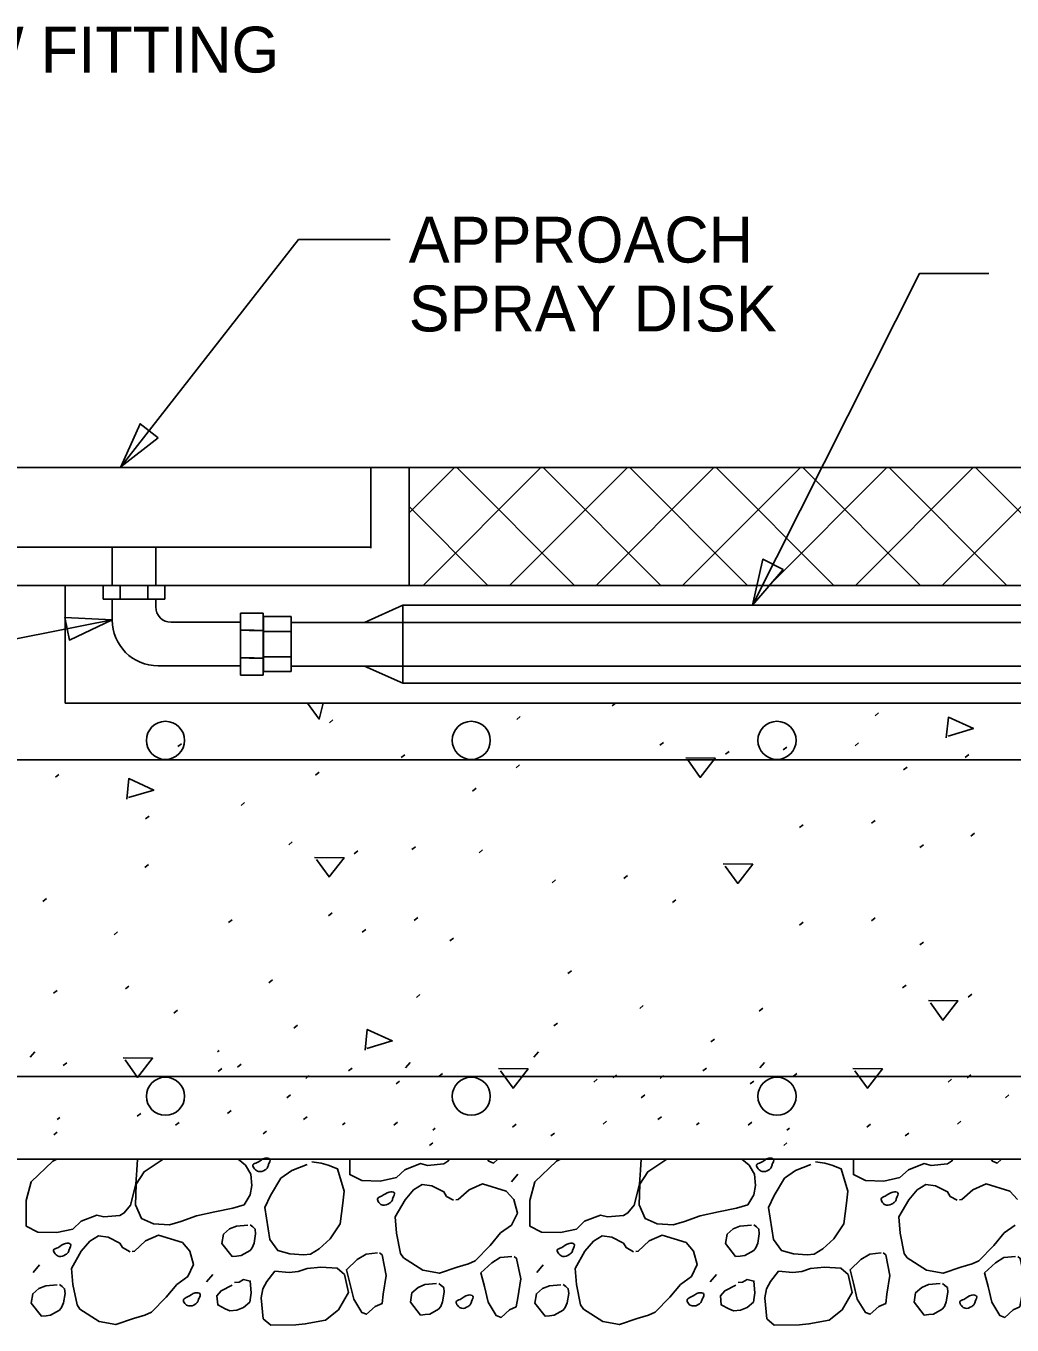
# Model space of a CAD drawing. Extents: x 3239 to 4230, y -4276 to -2494.
# Drawn here: x 3348.5 to 3413, y -4182.4 to -4097.4 of the extents above; entities that cross this region are included whole.
import ezdxf

# ---------------------------------------------------------------- set-up
doc = ezdxf.new("R2010")
doc.units = 0
doc.layers.add('2', color=7, linetype='Continuous')

msp = doc.modelspace()

# ---------------------------------------------------------------- linework, layer by layer
at = {"layer": '2'}
for p, q in [((3367.086, -4126.29), (3310.367, -4126.29)), ((3367.086, -4126.29), (3545.886, -4126.29)), ((3371.086, -4126.29), (3371.086, -4131.565)), ((3373.586, -4126.29), (3373.586, -4133.99)), ((3373.586, -4129.25), (3376.546, -4126.29)), ((3374.502, -4133.99), (3382.202, -4126.29)), ((3376.699, -4126.29), (3384.399, -4133.99)), ((3380.159, -4133.99), (3387.859, -4126.29)), ((3382.355, -4126.29), (3390.055, -4133.99)), ((3385.816, -4133.99), (3393.516, -4126.29)), ((3388.012, -4126.29), (3395.712, -4133.99)), ((3391.473, -4133.99), (3399.173, -4126.29)), ((3393.669, -4126.29), (3401.369, -4133.99)), ((3397.13, -4133.99), (3404.83, -4126.29)), ((3399.326, -4126.29), (3407.026, -4133.99)), ((3402.787, -4133.99), (3410.487, -4126.29)), ((3404.983, -4126.29), (3412.683, -4133.99)), ((3408.444, -4133.99), (3416.144, -4126.29)), ((3410.64, -4126.29), (3418.34, -4133.99)), ((3373.586, -4128.834), (3378.742, -4133.99)), ((3340.086, -4131.49), (3371.086, -4131.49)), ((3354.161, -4131.49), (3354.161, -4133.99)), ((3357.011, -4131.49), (3354.161, -4131.49)), ((3357.011, -4131.49), (3357.011, -4133.99)), ((3314.367, -4133.99), (3373.472, -4133.99)), ((3351.09, -4133.99), (3351.09, -4141.69)), ((3353.561, -4133.99), (3353.561, -4134.89)), ((3357.611, -4133.99), (3353.561, -4133.99)), ((3354.686, -4133.99), (3354.686, -4134.89)), ((3356.486, -4133.99), (3356.486, -4134.89)), ((3357.611, -4133.99), (3357.611, -4134.89)), ((3363.086, -4133.99), (3601.998, -4133.99)), ((3357.611, -4134.89), (3353.561, -4134.89)), ((3354.161, -4134.89), (3354.161, -4136.254)), ((3357.011, -4134.89), (3357.011, -4135.404)), ((3362.557, -4135.804), (3363.457, -4135.804)), ((3362.557, -4135.804), (3362.557, -4139.854)), ((3363.127, -4135.815), (3364.027, -4135.815)), ((3364.027, -4135.815), (3364.027, -4139.865)), ((3373.167, -4136.497), (3373.163, -4135.284)), ((3373.167, -4135.293), (3504.55, -4135.293)), ((3373.167, -4135.293), (3373.167, -4140.387)), ((3358.011, -4136.404), (3362.557, -4136.404)), ((3364.057, -4136.029), (3364.057, -4139.629)), ((3364.057, -4136.029), (3365.857, -4136.029)), ((3365.857, -4136.029), (3365.857, -4139.629)), ((3365.857, -4136.415), (3504.55, -4136.415)), ((3362.557, -4136.929), (3363.457, -4136.929)), ((3363.127, -4136.94), (3364.027, -4136.94)), ((3364.057, -4137.004), (3365.857, -4137.004)), ((3357.161, -4139.254), (3362.557, -4139.254)), ((3362.557, -4138.729), (3363.457, -4138.729)), ((3363.127, -4138.74), (3364.027, -4138.74)), ((3364.057, -4138.654), (3365.857, -4138.654)), ((3365.857, -4139.265), (3504.55, -4139.265)), ((3365.857, -4139.265), (3504.55, -4139.265)), ((3362.557, -4139.854), (3363.457, -4139.854)), ((3363.127, -4139.865), (3364.027, -4139.865)), ((3364.057, -4139.629), (3365.857, -4139.629)), ((3373.167, -4140.387), (3504.55, -4140.387)), ((3351.09, -4141.69), (3512.455, -4141.69)), ((3386.867, -4141.869), (3387.09, -4141.69)), ((3380.623, -4142.754), (3380.856, -4142.567)), ((3404.059, -4142.518), (3404.292, -4142.332)), ((3368.365, -4142.973), (3368.598, -4142.787)), ((3358.463, -4144.534), (3358.696, -4144.348)), ((3389.988, -4144.446), (3390.221, -4144.26)), ((3402.754, -4144.475), (3402.987, -4144.289)), ((3373.071, -4145.256), (3373.304, -4145.07)), ((3394.276, -4145.037), (3394.509, -4144.851)), ((3398.05, -4144.757), (3398.283, -4144.571)), ((3409.953, -4145.244), (3410.186, -4145.058)), ((3311.806, -4145.411), (3542.451, -4145.411)), ((3380.577, -4145.922), (3380.81, -4145.736)), ((3405.922, -4146.06), (3406.155, -4145.873)), ((3350.448, -4146.538), (3350.681, -4146.351)), ((3367.456, -4146.398), (3367.689, -4146.212)), ((3377.73, -4147.446), (3377.963, -4147.26)), ((3362.587, -4148.378), (3362.82, -4148.192)), ((3356.343, -4149.264), (3356.576, -4149.077)), ((3403.825, -4149.552), (3404.058, -4149.366)), ((3399.121, -4149.834), (3399.354, -4149.648)), ((3410.328, -4150.388), (3410.561, -4150.202)), ((3365.708, -4150.956), (3365.941, -4150.769)), ((3373.77, -4151.267), (3374.003, -4151.081)), ((3406.993, -4151.136), (3407.226, -4150.95)), ((3369.995, -4151.547), (3370.228, -4151.36)), ((3378.159, -4151.481), (3378.392, -4151.295)), ((3356.296, -4152.432), (3356.529, -4152.246)), ((3382.933, -4153.434), (3383.166, -4153.248)), ((3387.636, -4153.152), (3387.869, -4152.965)), ((3349.622, -4154.656), (3349.855, -4154.47)), ((3390.805, -4154.736), (3391.038, -4154.55)), ((3368.318, -4155.601), (3368.551, -4155.414)), ((3361.771, -4156.043), (3362.004, -4155.857)), ((3373.919, -4155.908), (3374.152, -4155.721)), ((3399.121, -4156.203), (3399.354, -4156.016)), ((3403.825, -4155.921), (3404.058, -4155.734)), ((3354.281, -4156.846), (3354.514, -4156.66)), ((3370.508, -4156.681), (3370.741, -4156.495)), ((3376.245, -4157.245), (3376.478, -4157.059)), ((3406.993, -4157.505), (3407.226, -4157.318)), ((3383.961, -4159.379), (3384.194, -4159.193)), ((3350.321, -4160.667), (3350.554, -4160.481)), ((3355.024, -4160.385), (3355.257, -4160.199)), ((3364.404, -4159.981), (3364.637, -4159.794)), ((3405.864, -4160.322), (3406.097, -4160.135)), ((3374.059, -4160.94), (3374.292, -4160.754)), ((3410.152, -4160.913), (3410.385, -4160.726)), ((3358.193, -4161.969), (3358.426, -4161.783)), ((3388.667, -4161.662), (3388.9, -4161.476)), ((3396.487, -4161.832), (3396.72, -4161.646)), ((3366.044, -4162.944), (3366.277, -4162.757)), ((3383.052, -4162.804), (3383.285, -4162.618)), ((3393.326, -4163.852), (3393.559, -4163.666)), ((3361.059, -4164.49), (3361.152, -4164.416)), ((3350.964, -4165.398), (3351.197, -4165.212)), ((3361.099, -4165.774), (3361.332, -4165.588)), ((3362.357, -4165.494), (3362.59, -4165.308)), ((3369.62, -4165.75), (3369.853, -4165.563)), ((3392.794, -4165.75), (3393.027, -4165.563)), ((3310.367, -4166.121), (3542.451, -4166.121)), ((3366.819, -4166.243), (3367.052, -4166.056)), ((3372.726, -4166.594), (3372.959, -4166.407)), ((3375.527, -4166.101), (3375.76, -4165.914)), ((3385.661, -4166.476), (3385.894, -4166.29)), ((3386.919, -4166.196), (3387.152, -4166.01)), ((3389.994, -4166.243), (3390.227, -4166.056)), ((3395.9, -4166.594), (3396.133, -4166.407)), ((3398.701, -4166.101), (3398.934, -4165.914)), ((3408.835, -4166.476), (3409.068, -4166.29)), ((3410.094, -4166.196), (3410.327, -4166.01)), ((3365.585, -4167.505), (3365.818, -4167.318)), ((3388.759, -4167.505), (3388.992, -4167.318)), ((3412.587, -4167.505), (3412.819, -4167.318)), ((3350.561, -4168.929), (3350.734, -4168.791)), ((3355.793, -4168.713), (3356.026, -4168.527)), ((3361.709, -4168.524), (3361.942, -4168.338)), ((3366.68, -4168.934), (3366.913, -4168.747)), ((3386.271, -4169.226), (3386.504, -4169.04)), ((3389.854, -4168.934), (3390.087, -4168.747)), ((3409.445, -4169.226), (3409.678, -4169.04)), ((3350.35, -4169.92), (3350.561, -4169.751)), ((3358.298, -4169.297), (3358.531, -4169.111)), ((3364.035, -4169.861), (3364.246, -4169.692)), ((3369.217, -4169.28), (3369.39, -4169.142)), ((3372.586, -4169.285), (3372.819, -4169.098)), ((3375.124, -4169.632), (3375.296, -4169.493)), ((3380.356, -4169.415), (3380.589, -4169.229)), ((3382.86, -4170), (3383.093, -4169.813)), ((3392.391, -4169.28), (3392.564, -4169.142)), ((3395.761, -4169.285), (3395.994, -4169.098)), ((3398.298, -4169.632), (3398.47, -4169.493)), ((3403.53, -4169.415), (3403.763, -4169.229)), ((3406.035, -4170), (3406.268, -4169.813)), ((3374.913, -4170.622), (3375.124, -4170.453)), ((3398.087, -4170.622), (3398.298, -4170.453)), ((3310.367, -4171.521), (3545.886, -4171.521))]:
    msp.add_line(p, q, dxfattribs=at)
for points in [[(3354.161, -4136.254), (3336.608, -4139.711), (3316.512, -4098.7), (3322.282, -4098.7)], [(3354.724, -4126.244), (3366.348, -4111.379), (3372.342, -4111.379)], [(3396.034, -4135.293), (3406.964, -4113.601), (3411.503, -4113.601)], [(3367.951, -4141.69), (3367.708, -4142.732), (3366.934, -4141.69)], [(3408.718, -4143.963), (3408.858, -4142.611), (3410.489, -4143.357), (3408.835, -4143.846)], [(3391.673, -4145.27), (3393.607, -4145.293), (3392.628, -4146.551), (3391.813, -4145.41)], [(3355.108, -4147.982), (3355.248, -4146.631), (3356.879, -4147.376), (3355.225, -4147.866)], [(3367.392, -4151.78), (3369.326, -4151.803), (3368.348, -4153.061), (3367.532, -4151.919)], [(3394.127, -4152.205), (3396.06, -4152.229), (3395.082, -4153.487), (3394.266, -4152.345)], [(3407.549, -4161.145), (3409.482, -4161.169), (3408.504, -4162.427), (3407.688, -4161.285)], [(3370.704, -4164.388), (3370.844, -4163.037), (3372.475, -4163.783), (3370.82, -4164.272)], [(3349.093, -4164.49), (3348.789, -4164.853)], [(3382.037, -4164.49), (3381.733, -4164.853)], [(3354.868, -4164.892), (3356.802, -4164.915), (3355.823, -4166.173), (3355.008, -4165.032)], [(3373.656, -4165.192), (3373.352, -4165.555)], [(3379.431, -4165.594), (3381.364, -4165.618), (3380.386, -4166.876), (3379.57, -4165.734)], [(3396.83, -4165.192), (3396.526, -4165.555)], [(3402.605, -4165.594), (3404.538, -4165.618), (3403.56, -4166.876), (3402.745, -4165.734)], [(3350.53, -4171.521), (3350.274, -4171.649), (3348.867, -4172.992), (3348.538, -4174.218), (3348.532, -4175.898), (3349.307, -4176.287), (3350.53, -4176.31), (3351.579, -4176.088), (3352.122, -4175.584), (3353.155, -4175.188), (3353.622, -4175.299), (3354.66, -4175.208), (3354.95, -4175.031), (3355.364, -4174.537), (3355.702, -4173.156), (3355.773, -4172.236), (3355.812, -4171.521)], [(3357.504, -4171.521), (3356.262, -4172.345), (3355.723, -4173.154), (3355.688, -4174.509), (3356.071, -4175.39), (3356.865, -4175.756), (3357.917, -4175.817), (3358.66, -4175.599), (3359.674, -4175.228), (3360.871, -4174.97), (3362.049, -4174.715), (3362.792, -4174.496), (3363.193, -4173.852), (3363.292, -4173.233), (3363.228, -4172.498), (3362.872, -4171.918), (3362.396, -4171.521)], [(3369.705, -4171.521), (3369.7, -4172.521), (3370.497, -4172.908), (3371.7, -4172.955), (3372.747, -4172.711), (3373.312, -4172.205), (3374.323, -4171.811), (3374.792, -4171.922), (3375.85, -4171.829), (3376.118, -4171.654), (3376.235, -4171.521)], [(3378.72, -4171.521), (3378.797, -4171.647), (3379.113, -4171.771), (3379.383, -4171.521)], [(3383.474, -4171.521), (3383.218, -4171.649), (3381.81, -4172.992), (3381.482, -4174.218), (3381.476, -4175.898), (3382.25, -4176.287), (3383.474, -4176.31), (3384.522, -4176.088), (3385.065, -4175.584), (3386.099, -4175.188), (3386.566, -4175.299), (3387.604, -4175.208), (3387.894, -4175.031), (3388.308, -4174.537), (3388.646, -4173.156), (3388.717, -4172.236), (3388.756, -4171.521)], [(3390.448, -4171.521), (3389.205, -4172.345), (3388.667, -4173.154), (3388.632, -4174.509), (3389.015, -4175.39), (3389.809, -4175.756), (3390.861, -4175.817), (3391.604, -4175.599), (3392.618, -4175.228), (3393.815, -4174.97), (3394.992, -4174.715), (3395.736, -4174.496), (3396.136, -4173.852), (3396.236, -4173.233), (3396.172, -4172.498), (3395.815, -4171.918), (3395.34, -4171.521)], [(3402.649, -4171.521), (3402.644, -4172.521), (3403.44, -4172.908), (3404.644, -4172.955), (3405.691, -4172.711), (3406.255, -4172.205), (3407.267, -4171.811), (3407.736, -4171.922), (3408.794, -4171.829), (3409.062, -4171.654), (3409.179, -4171.521)], [(3411.664, -4171.521), (3411.741, -4171.647), (3412.057, -4171.771), (3412.327, -4171.521)], [(3366.92, -4171.869), (3365.909, -4172.263), (3365.19, -4172.762), (3364.526, -4173.888), (3364.138, -4174.684), (3364.472, -4176.769), (3364.992, -4177.486), (3365.774, -4177.701), (3366.674, -4177.774), (3367.128, -4177.734), (3367.708, -4177.38), (3368.413, -4176.729), (3369.069, -4175.756), (3369.255, -4174.39), (3369.339, -4173.62), (3368.906, -4172.153), (3368.296, -4171.903), (3367.828, -4171.79), (3367.21, -4171.692)], [(3399.864, -4171.869), (3398.852, -4172.263), (3398.133, -4172.762), (3397.469, -4173.888), (3397.082, -4174.684), (3397.416, -4176.769), (3397.936, -4177.486), (3398.717, -4177.701), (3399.618, -4177.774), (3400.072, -4177.734), (3400.652, -4177.38), (3401.357, -4176.729), (3402.013, -4175.756), (3402.199, -4174.39), (3402.283, -4173.62), (3401.849, -4172.153), (3401.24, -4171.903), (3400.771, -4171.79), (3400.154, -4171.692)], [(3376.494, -4174.192), (3376.035, -4173.949), (3375.858, -4173.659), (3375.062, -4173.271), (3374.443, -4173.174), (3373.865, -4173.528), (3373.333, -4174.185), (3372.667, -4175.289), (3372.76, -4176.349), (3373.028, -4177.677), (3373.207, -4177.967), (3374.475, -4178.77), (3375.561, -4178.981), (3376.724, -4178.574), (3377.467, -4178.357), (3377.909, -4178.164), (3378.89, -4177.164), (3379.559, -4176.343), (3380.277, -4175.843), (3380.665, -4175.047), (3380.435, -4174.153), (3379.928, -4173.608), (3378.383, -4173.132), (3377.503, -4173.515), (3376.795, -4174.166), (3376.645, -4174.179)], [(3380.691, -4172.507), (3380.275, -4173.003)], [(3409.438, -4174.192), (3408.979, -4173.949), (3408.802, -4173.659), (3408.006, -4173.271), (3407.386, -4173.174), (3406.808, -4173.528), (3406.277, -4174.185), (3405.611, -4175.289), (3405.704, -4176.349), (3405.972, -4177.677), (3406.151, -4177.967), (3407.419, -4178.77), (3408.505, -4178.981), (3409.667, -4178.574), (3410.411, -4178.357), (3410.853, -4178.164), (3411.833, -4177.164), (3412.502, -4176.343), (3413.221, -4175.843)], [(3413.379, -4174.153), (3412.872, -4173.608), (3411.327, -4173.132), (3410.446, -4173.515), (3409.739, -4174.166), (3409.588, -4174.179)], [(3363.038, -4175.826), (3362.282, -4175.893), (3361.841, -4176.085), (3361.436, -4176.424), (3361.336, -4177.043), (3361.998, -4177.88), (3362.301, -4177.853), (3362.604, -4177.827), (3363.184, -4177.492), (3363.323, -4177.327), (3363.447, -4177.012), (3363.545, -4176.393), (3363.519, -4176.09), (3363.355, -4175.952), (3363.191, -4175.813)], [(3395.982, -4175.826), (3395.225, -4175.893), (3394.785, -4176.085), (3394.379, -4176.424), (3394.28, -4177.043), (3394.942, -4177.88), (3395.245, -4177.853), (3395.548, -4177.827), (3396.128, -4177.492), (3396.267, -4177.327), (3396.391, -4177.012), (3396.489, -4176.393), (3396.462, -4176.09), (3396.299, -4175.952), (3396.135, -4175.813)], [(3355.326, -4177.569), (3354.844, -4177.306), (3354.666, -4177.016), (3353.892, -4176.627), (3353.272, -4176.529), (3352.693, -4176.885), (3352.141, -4177.542), (3351.499, -4178.666), (3351.59, -4179.705), (3351.859, -4181.054), (3352.037, -4181.322), (3353.305, -4182.126), (3354.391, -4182.336), (3355.553, -4181.929), (3356.297, -4181.712), (3356.737, -4181.52), (3357.698, -4180.543), (3358.388, -4179.721), (3359.107, -4179.201), (3359.473, -4178.404), (3359.243, -4177.532), (3358.758, -4176.963), (3357.192, -4176.492), (3356.33, -4176.87), (3355.627, -4177.543), (3355.476, -4177.556)], [(3388.269, -4177.569), (3387.787, -4177.306), (3387.61, -4177.016), (3386.835, -4176.627), (3386.216, -4176.529), (3385.636, -4176.885), (3385.085, -4177.542), (3384.443, -4178.666), (3384.533, -4179.705), (3384.803, -4181.054), (3384.98, -4181.322), (3386.249, -4182.126), (3387.335, -4182.336), (3388.497, -4181.929), (3389.241, -4181.712), (3389.681, -4181.52), (3390.642, -4180.543), (3391.332, -4179.721), (3392.051, -4179.201), (3392.417, -4178.404), (3392.187, -4177.532), (3391.702, -4176.963), (3390.135, -4176.492), (3389.274, -4176.87), (3388.571, -4177.543), (3388.42, -4177.556)], [(3371.523, -4177.655), (3370.766, -4177.722), (3370.186, -4178.078), (3369.483, -4178.75), (3369.713, -4179.622), (3369.956, -4180.669), (3370.489, -4181.538), (3370.805, -4181.663), (3371.372, -4181.156), (3371.812, -4180.964), (3371.888, -4180.348), (3372.087, -4179.131), (3371.818, -4177.783), (3371.652, -4177.644)], [(3380.299, -4177.888), (3379.54, -4177.955), (3378.984, -4178.309), (3378.278, -4178.959), (3378.508, -4179.854), (3378.752, -4180.878), (3379.285, -4181.748), (3379.601, -4181.872), (3380.144, -4181.367), (3380.586, -4181.175), (3380.686, -4180.579), (3380.883, -4179.34), (3380.613, -4178.014), (3380.449, -4177.875)], [(3404.466, -4177.655), (3403.71, -4177.722), (3403.13, -4178.078), (3402.426, -4178.75), (3402.656, -4179.622), (3402.9, -4180.669), (3403.433, -4181.538), (3403.749, -4181.663), (3404.316, -4181.156), (3404.756, -4180.964), (3404.832, -4180.348), (3405.031, -4179.131), (3404.761, -4177.783), (3404.596, -4177.644)], [(3413.242, -4177.888), (3412.484, -4177.955), (3411.928, -4178.309), (3411.222, -4178.959), (3411.452, -4179.854), (3411.695, -4180.878), (3412.229, -4181.748), (3412.545, -4181.872), (3413.088, -4181.367), (3413.53, -4181.175), (3413.63, -4180.579), (3413.827, -4179.34), (3413.557, -4178.014), (3413.393, -4177.875)], [(3349.414, -4178.429), (3348.998, -4178.924)], [(3360.75, -4179.057), (3360.336, -4179.55)], [(3365.729, -4178.925), (3364.807, -4178.854), (3364.277, -4179.511), (3364.013, -4179.991), (3363.912, -4180.587), (3364.031, -4181.95), (3364.527, -4182.365), (3366.18, -4182.351), (3366.786, -4182.298), (3368.116, -4182.051), (3368.971, -4181.366), (3369.613, -4180.242), (3369.359, -4179.066), (3368.887, -4178.648), (3367.814, -4178.591), (3366.905, -4178.67), (3366.335, -4178.872), (3365.729, -4178.925)], [(3382.357, -4178.429), (3381.942, -4178.924)], [(3393.694, -4179.057), (3393.28, -4179.55)], [(3398.673, -4178.925), (3397.75, -4178.854), (3397.221, -4179.511), (3396.957, -4179.991), (3396.856, -4180.587), (3396.975, -4181.95), (3397.47, -4182.365), (3399.124, -4182.351), (3399.73, -4182.298), (3401.06, -4182.051), (3401.914, -4181.366), (3402.557, -4180.242), (3402.302, -4179.066), (3401.83, -4178.648), (3400.757, -4178.591), (3399.848, -4178.67), (3399.279, -4178.872), (3398.673, -4178.925)], [(3350.569, -4179.727), (3349.813, -4179.794), (3349.372, -4179.986), (3348.966, -4180.325), (3348.867, -4180.944), (3349.529, -4181.781), (3349.832, -4181.754), (3350.135, -4181.728), (3350.715, -4181.393), (3350.854, -4181.228), (3350.978, -4180.913), (3351.076, -4180.294), (3351.049, -4179.991), (3350.886, -4179.853), (3350.722, -4179.714)], [(3362.014, -4179.75), (3361.283, -4180.12), (3361.009, -4180.449), (3361.061, -4181.053), (3361.542, -4181.317), (3361.858, -4181.443), (3362.312, -4181.403), (3362.752, -4181.211), (3363.158, -4180.87), (3363.257, -4180.252), (3363.191, -4179.496), (3362.746, -4179.381), (3362.456, -4179.56), (3362.153, -4179.586)], [(3375.368, -4179.658), (3374.612, -4179.724), (3374.171, -4179.916), (3373.765, -4180.255), (3373.666, -4180.875), (3374.328, -4181.711), (3374.631, -4181.685), (3374.934, -4181.658), (3375.514, -4181.324), (3375.653, -4181.158), (3375.777, -4180.843), (3375.875, -4180.224), (3375.848, -4179.921), (3375.685, -4179.784), (3375.521, -4179.644)], [(3383.513, -4179.727), (3382.756, -4179.794), (3382.316, -4179.986), (3381.91, -4180.325), (3381.811, -4180.944), (3382.473, -4181.781), (3382.776, -4181.754), (3383.079, -4181.728), (3383.659, -4181.393), (3383.798, -4181.228), (3383.922, -4180.913), (3384.02, -4180.294), (3383.993, -4179.991), (3383.829, -4179.853), (3383.665, -4179.714)], [(3394.957, -4179.75), (3394.227, -4180.12), (3393.952, -4180.449), (3394.005, -4181.053), (3394.485, -4181.317), (3394.802, -4181.443), (3395.255, -4181.403), (3395.696, -4181.211), (3396.101, -4180.87), (3396.201, -4180.252), (3396.135, -4179.496), (3395.689, -4179.381), (3395.4, -4179.56), (3395.097, -4179.586)], [(3408.312, -4179.658), (3407.555, -4179.724), (3407.115, -4179.916), (3406.709, -4180.255), (3406.61, -4180.875), (3407.272, -4181.711), (3407.575, -4181.685), (3407.878, -4181.658), (3408.458, -4181.324), (3408.597, -4181.158), (3408.721, -4180.843), (3408.819, -4180.224), (3408.792, -4179.921), (3408.628, -4179.784), (3408.464, -4179.644)]]:
    msp.add_lwpolyline(points, dxfattribs=at)
for points in [[(3357.163, -4124.343), (3354.724, -4126.244), (3355.981, -4123.419)], [(3373.586, -4133.99), (3545.886, -4133.99), (3545.886, -4126.29), (3373.586, -4126.29)], [(3398.054, -4132.951), (3396.034, -4135.293), (3396.714, -4132.276)], [(3373.163, -4135.284), (3373.167, -4136.415), (3370.675, -4136.415)], [(3351.072, -4136.098), (3354.161, -4136.254), (3351.362, -4137.57)], [(3370.663, -4139.265), (3373.164, -4139.272), (3373.167, -4140.387)]]:
    msp.add_lwpolyline(points, close=True, dxfattribs=at)
for centre in [(3357.646, -4144.128), (3377.646, -4144.128), (3397.646, -4144.128), (3357.646, -4167.404), (3377.646, -4167.404), (3397.646, -4167.404)]:
    msp.add_circle(centre, 1.247, dxfattribs=at)
for centre, radius in [((3358.011, -4135.404), 1), ((3357.161, -4136.254), 3)]:
    msp.add_arc(centre, radius, 180, 270, dxfattribs=at)
for points in [[(3364.391, -4171.852), (3364.322, -4172.053), (3364.161, -4172.221), (3363.735, -4172.323), (3363.479, -4172.149), (3363.37, -4171.896), (3363.641, -4171.743), (3364.159, -4171.457), (3364.47, -4171.518), (3364.371, -4171.876)], [(3397.335, -4171.852), (3397.266, -4172.053), (3397.105, -4172.221), (3396.678, -4172.323), (3396.423, -4172.149), (3396.314, -4171.896), (3396.584, -4171.743), (3397.103, -4171.457), (3397.414, -4171.518), (3397.315, -4171.876)], [(3372.516, -4174.061), (3372.445, -4174.263), (3372.285, -4174.407), (3371.86, -4174.532), (3371.605, -4174.358), (3371.517, -4174.104), (3371.786, -4173.928), (3372.285, -4173.666), (3372.617, -4173.725), (3372.516, -4174.061)], [(3405.46, -4174.061), (3405.389, -4174.263), (3405.228, -4174.407), (3404.804, -4174.532), (3404.548, -4174.358), (3404.461, -4174.104), (3404.729, -4173.928), (3405.229, -4173.666), (3405.561, -4173.725), (3405.46, -4174.061)], [(3351.346, -4177.417), (3351.275, -4177.618), (3351.114, -4177.764), (3350.69, -4177.888), (3350.434, -4177.713), (3350.326, -4177.463), (3350.596, -4177.307), (3351.115, -4177.023), (3351.425, -4177.083), (3351.348, -4177.438)], [(3384.29, -4177.417), (3384.219, -4177.618), (3384.058, -4177.764), (3383.634, -4177.888), (3383.378, -4177.713), (3383.269, -4177.463), (3383.539, -4177.307), (3384.058, -4177.023), (3384.369, -4177.083), (3384.292, -4177.438)], [(3359.821, -4180.641), (3359.751, -4180.843), (3359.591, -4181.01), (3359.164, -4181.113), (3358.912, -4180.959), (3358.824, -4180.707), (3359.092, -4180.53), (3359.593, -4180.269), (3359.9, -4180.307), (3359.822, -4180.663)], [(3377.674, -4180.803), (3377.603, -4181.004), (3377.442, -4181.15), (3377.018, -4181.274), (3376.762, -4181.099), (3376.654, -4180.849), (3376.924, -4180.693), (3377.442, -4180.407), (3377.753, -4180.469), (3377.654, -4180.826)], [(3392.764, -4180.641), (3392.695, -4180.843), (3392.535, -4181.01), (3392.108, -4181.113), (3391.856, -4180.959), (3391.767, -4180.707), (3392.035, -4180.53), (3392.537, -4180.269), (3392.844, -4180.307), (3392.766, -4180.663)], [(3410.618, -4180.803), (3410.547, -4181.004), (3410.386, -4181.15), (3409.962, -4181.274), (3409.706, -4181.099), (3409.597, -4180.849), (3409.867, -4180.693), (3410.386, -4180.407), (3410.697, -4180.469), (3410.598, -4180.826)]]:
    msp.add_spline(points, degree=3, dxfattribs=at)

# ---------------------------------------------------------------- texts
for s, p in [('NEW ELBOW FITTING', (3323.412, -4100.448)), ('APPROACH', (3373.558, -4112.879)), ('SPRAY DISK', (3373.558, -4117.379))]:
    msp.add_text(s, height=3, dxfattribs=at).set_placement(p)

doc.saveas('drawing.dxf')
